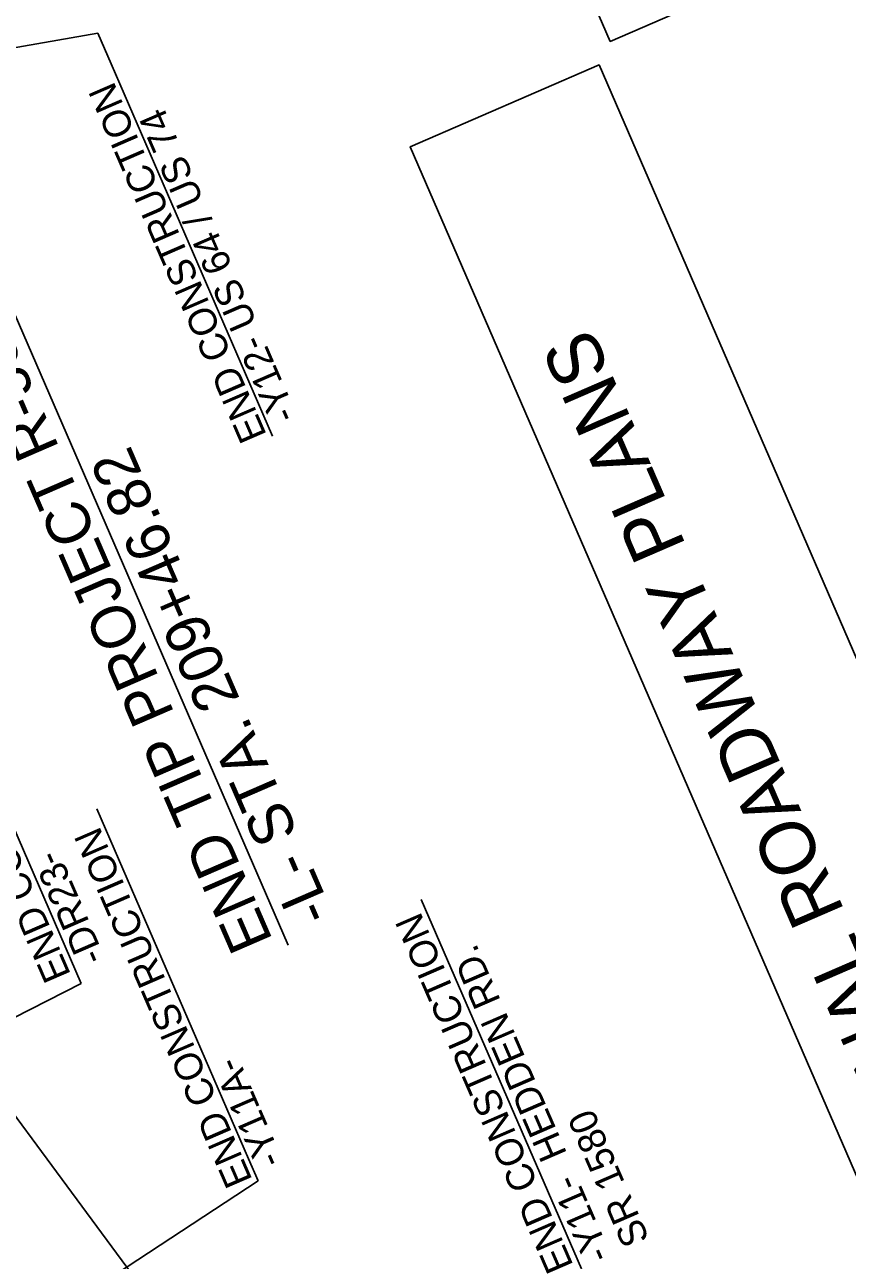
# Model space of a CAD drawing. Extents: x 442728 to 492797, y 479541 to 511293.
# Drawn here: x 475625 to 478444, y 502835 to 507069 of the extents above; entities that cross this region are included whole.
import ezdxf

# ---------------------------------------------------------------- set-up
doc = ezdxf.new("R2010")
doc.units = 0
for name, color, linetype in [('Default', 7, 'Continuous'), ('Prop DSN Text', 7, 'Continuous'), ('Prop PHM Text', 7, 'Continuous'), ('Sheet Plan Layout CELL', 7, 'Continuous'), ('Sheet Sticker Incomplete CELL', 7, 'Continuous')]:
    doc.layers.add(name, color=color, linetype=linetype)

msp = doc.modelspace()

# ---------------------------------------------------------------- linework, layer by layer
at = {"layer": 'Default'}
msp.add_line((476528.1, 503914.7), (475426.5, 506455.2), dxfattribs=at)
at = {"layer": 'Prop DSN Text'}
for p, q in [((475875.2, 507039.8), (474361.8, 506777.4)), ((475920.9, 506934.5), (475875.2, 507039.8)), ((476441, 505735.1), (475920.9, 506934.5)), ((476473.8, 505659.3), (476441, 505735.1)), ((475233.1, 505133.5), (475818.4, 503783.6)), ((476392.1, 503182.4), (475872, 504381.9)), ((477532.9, 502805.5), (476984.2, 504070.8)), ((475818.4, 503783.6), (474961.8, 503346.7)), ((476424.9, 503106.6), (476392.1, 503182.4)), ((476424.9, 503106.6), (475759.8, 502670.7))]:
    msp.add_line(p, q, dxfattribs=at)
at = {"layer": 'Prop PHM Text'}
msp.add_lwpolyline([(478984.7, 501949.8), (476946.4, 506650.5), (477593, 506930.9), (479631.3, 502230.2)], close=True, dxfattribs=at)
at = {"layer": 'Sheet Plan Layout CELL'}
msp.add_lwpolyline([(476077.7, 502671.6), (475233, 502047.8), (474564.7, 502952.8), (474564.8, 502952.8), (474342, 503254.4), (475186.7, 503878.2)], close=True, dxfattribs=at)
at = {"layer": 'Sheet Sticker Incomplete CELL'}
msp.add_lwpolyline([(477955.1, 507152.1), (477631.7, 507011.8), (476754.4, 509034.8), (477077.9, 509175.1)], close=True, dxfattribs=at)

# ---------------------------------------------------------------- texts
at = {"layer": 'Default'}
for s, p in [('END TIP PROJECT R-5861', (476476.6, 503930.9)), ('-L- STA. 209+46.82', (476683.1, 504020.5))]:
    msp.add_text(s, height=150, rotation=113.4424, dxfattribs=at).set_placement(p)
at = {"layer": 'Prop DSN Text'}
for s, height, p in [('END CONSTRUCTION', 94.918, (476455.5, 505662.5)), ('-Y12- US 64 / US 74', 94.918, (476560.4, 505728.2)), ('END CONSTRUCTION', 94.918, (475784.4, 503813.3)), ('END CONSTRUCTION', 94.918, (476406.6, 503109.8)), ('-DR23- ', 94.92, (475901.3, 503870.9)), ('END CONSTRUCTION', 94.918, (477506.4, 502816.7)), ('-Y11-  HEDDEN RD.', 94.918, (477636.2, 502850.1)), ('-Y11A- ', 94.92, (476511.5, 503175.5)), ('SR 1580', 94.92, (477766.8, 502906.7))]:
    msp.add_text(s, height=height, rotation=113.4424, dxfattribs=at).set_placement(p)
at = {"layer": 'Prop PHM Text'}
msp.add_text('S-071R1 : FINAL ROADWAY PLANS', height=187.5, rotation=113.4406, dxfattribs=at).set_placement((479223.3, 502213.8))

doc.saveas('drawing.dxf')
